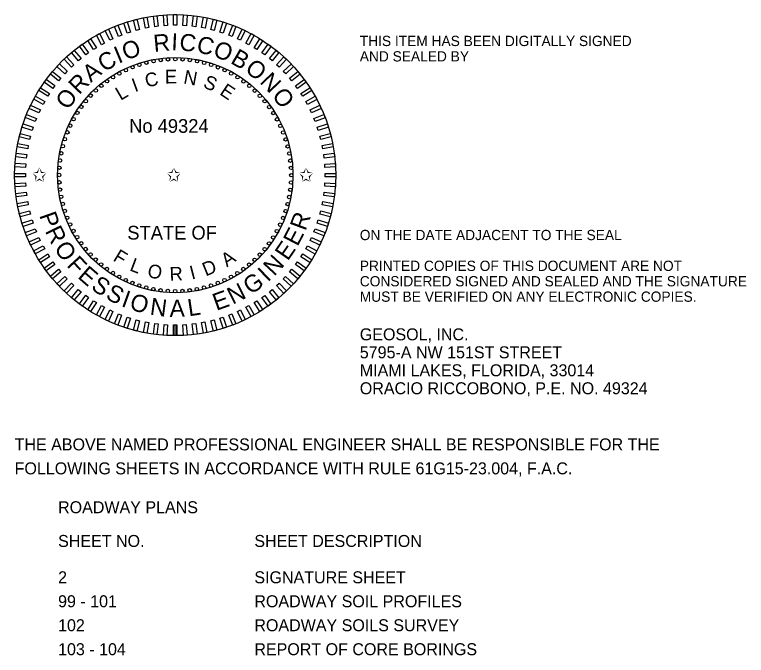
# Model space of a CAD drawing. Extents: x -811 to -790, y -2284 to -2178.
# Drawn here: x -794.327 to -790.055, y -2192.952 to -2189.209 of the extents above; entities that cross this region are included whole.
import ezdxf

# ---------------------------------------------------------------- set-up
doc = ezdxf.new("R2010")
doc.units = 0
for name, color, linetype in [('PlotBorder_dp', 7, 'Continuous'), ('TextMinor', 7, 'Continuous'), ('TextMisc', 7, 'Continuous'), ('TextShtNo', 7, 'Continuous')]:
    doc.layers.add(name, color=color, linetype=linetype)

msp = doc.modelspace()

# ---------------------------------------------------------------- linework, layer by layer
at = {"layer": 'TextMinor'}
for radius in [0.9375, 0.6875]:
    msp.add_circle((-793.3899, -2190.1468), radius, dxfattribs=at)
at = {"layer": 'TextShtNo'}
for p, q in [((-793.3999, -2191.0843), (-793.4001, -2191.0218)), ((-793.3899, -2191.0843), (-793.3901, -2191.0218)), ((-793.3799, -2191.0843), (-793.3801, -2191.0218))]:
    msp.add_line(p, q, dxfattribs=at)
for points in [[(-793.5976, -2189.2967), (-793.6172, -2189.3018), (-793.6327, -2189.2413), (-793.6132, -2189.2363)], [(-793.5438, -2189.2854), (-793.5637, -2189.2892), (-793.5754, -2189.2278), (-793.5555, -2189.224)], [(-793.4895, -2189.2774), (-793.5095, -2189.2799), (-793.5173, -2189.218), (-793.4973, -2189.2155)], [(-793.4347, -2189.2729), (-793.4548, -2189.2741), (-793.4587, -2189.2118), (-793.4386, -2189.2106)], [(-793.3797, -2189.2718), (-793.3999, -2189.2718), (-793.3999, -2189.2093), (-793.3797, -2189.2093)], [(-793.3248, -2189.2741), (-793.3449, -2189.2729), (-793.341, -2189.2106), (-793.3209, -2189.2118)], [(-793.2701, -2189.28), (-793.2901, -2189.2774), (-793.2823, -2189.2155), (-793.2623, -2189.218)], [(-793.2159, -2189.2892), (-793.2357, -2189.2854), (-793.224, -2189.2241), (-793.2042, -2189.2279)], [(-793.1624, -2189.3018), (-793.182, -2189.2968), (-793.1664, -2189.2363), (-793.1469, -2189.2413)], [(-793.7025, -2189.3295), (-793.7213, -2189.3369), (-793.7443, -2189.2789), (-793.7255, -2189.2714)], [(-793.6506, -2189.3115), (-793.6698, -2189.3177), (-793.6891, -2189.2583), (-793.6699, -2189.2521)], [(-793.1098, -2189.3178), (-793.129, -2189.3115), (-793.1097, -2189.2521), (-793.0905, -2189.2584)], [(-793.0583, -2189.337), (-793.0771, -2189.3295), (-793.0541, -2189.2715), (-793.0353, -2189.2789)], [(-793.8025, -2189.3751), (-793.8202, -2189.3848), (-793.8503, -2189.3301), (-793.8326, -2189.3204)], [(-793.7532, -2189.3507), (-793.7715, -2189.3593), (-793.7981, -2189.3028), (-793.7798, -2189.2942)], [(-793.0081, -2189.3594), (-793.0264, -2189.3508), (-792.9998, -2189.2943), (-792.9815, -2189.3029)], [(-792.9594, -2189.3849), (-792.9771, -2189.3752), (-792.947, -2189.3205), (-792.9293, -2189.3302)], [(-793.8502, -2189.4025), (-793.8672, -2189.4134), (-793.9007, -2189.3606), (-793.8836, -2189.3498)], [(-792.9124, -2189.4135), (-792.9295, -2189.4026), (-792.896, -2189.3499), (-792.879, -2189.3607)], [(-793.896, -2189.4329), (-793.9123, -2189.4448), (-793.949, -2189.3943), (-793.9327, -2189.3824)], [(-792.8673, -2189.4449), (-792.8836, -2189.433), (-792.8469, -2189.3825), (-792.8306, -2189.3944)], [(-793.9815, -2189.502), (-793.9962, -2189.5158), (-794.0389, -2189.4703), (-794.0242, -2189.4565)], [(-793.9398, -2189.4661), (-793.9554, -2189.479), (-793.9952, -2189.4309), (-793.9796, -2189.418)], [(-792.8243, -2189.4791), (-792.8398, -2189.4662), (-792.8, -2189.4181), (-792.7845, -2189.431)], [(-792.7835, -2189.5159), (-792.7982, -2189.5021), (-792.7554, -2189.4566), (-792.7407, -2189.4704)], [(-794.0208, -2189.5404), (-794.0346, -2189.5551), (-794.0801, -2189.5124), (-794.0663, -2189.4976)], [(-792.745, -2189.5552), (-792.7589, -2189.5405), (-792.7133, -2189.4978), (-792.6995, -2189.5125)], [(-794.0576, -2189.5812), (-794.0705, -2189.5968), (-794.1186, -2189.5569), (-794.1057, -2189.5414)], [(-792.7092, -2189.5969), (-792.722, -2189.5813), (-792.6739, -2189.5415), (-792.6611, -2189.5571)], [(-794.0918, -2189.6242), (-794.1037, -2189.6406), (-794.1542, -2189.6039), (-794.1423, -2189.5875)], [(-792.676, -2189.6407), (-792.6878, -2189.6244), (-792.6373, -2189.5877), (-792.6255, -2189.604)], [(-794.1232, -2189.6693), (-794.1341, -2189.6864), (-794.1868, -2189.6529), (-794.176, -2189.6359)], [(-792.6456, -2189.6865), (-792.6564, -2189.6695), (-792.6037, -2189.636), (-792.5929, -2189.6531)], [(-794.1518, -2189.7163), (-794.1615, -2189.734), (-794.2162, -2189.7039), (-794.2065, -2189.6863)], [(-792.6182, -2189.7342), (-792.6279, -2189.7165), (-792.5732, -2189.6864), (-792.5635, -2189.7041)], [(-794.1773, -2189.765), (-794.1859, -2189.7833), (-794.2424, -2189.7567), (-794.2338, -2189.7384)], [(-792.5938, -2189.7835), (-792.6024, -2189.7652), (-792.5459, -2189.7386), (-792.5373, -2189.7569)], [(-794.1997, -2189.8152), (-794.2071, -2189.834), (-794.2652, -2189.811), (-794.2578, -2189.7922)], [(-792.5726, -2189.8342), (-792.58, -2189.8154), (-792.5219, -2189.7924), (-792.5145, -2189.8112)], [(-794.2189, -2189.8667), (-794.2252, -2189.8859), (-794.2846, -2189.8666), (-794.2783, -2189.8474)], [(-792.5545, -2189.8861), (-792.5608, -2189.8669), (-792.5014, -2189.8476), (-792.4952, -2189.8668)], [(-794.2349, -2189.9193), (-794.2399, -2189.9389), (-794.3004, -2189.9234), (-794.2954, -2189.9038)], [(-792.5398, -2189.9391), (-792.5448, -2189.9195), (-792.4844, -2189.904), (-792.4793, -2189.9235)], [(-794.2475, -2189.9728), (-794.2513, -2189.9927), (-794.3126, -2189.981), (-794.3088, -2189.9611)], [(-792.5284, -2189.9929), (-792.5322, -2189.973), (-792.4709, -2189.9613), (-792.4671, -2189.9812)], [(-794.2567, -2190.027), (-794.2593, -2190.0471), (-794.3212, -2190.0392), (-794.3187, -2190.0192)], [(-792.5205, -2190.0472), (-792.523, -2190.0272), (-792.4611, -2190.0194), (-792.4585, -2190.0394)], [(-794.2626, -2190.0817), (-794.2638, -2190.1018), (-794.3261, -2190.0979), (-794.3249, -2190.0778)], [(-792.5159, -2190.102), (-792.5172, -2190.0819), (-792.4549, -2190.078), (-792.4536, -2190.0981)], [(-794.2649, -2190.1366), (-794.2649, -2190.1568), (-794.3274, -2190.1568), (-794.3274, -2190.1366)], [(-792.5149, -2190.157), (-792.5149, -2190.1368), (-792.4524, -2190.1368), (-792.4524, -2190.157)], [(-794.2638, -2190.1916), (-794.2626, -2190.2117), (-794.3249, -2190.2157), (-794.3261, -2190.1955)], [(-792.5172, -2190.2119), (-792.516, -2190.1918), (-792.4536, -2190.1957), (-792.4549, -2190.2158)], [(-794.2593, -2190.2464), (-794.2568, -2190.2664), (-794.3187, -2190.2742), (-794.3212, -2190.2542)], [(-792.523, -2190.2666), (-792.5205, -2190.2466), (-792.4586, -2190.2544), (-792.4611, -2190.2744)], [(-794.2513, -2190.3008), (-794.2475, -2190.3206), (-794.3089, -2190.3323), (-794.3127, -2190.3125)], [(-792.5323, -2190.3208), (-792.5285, -2190.301), (-792.4671, -2190.3127), (-792.4709, -2190.3325)], [(-794.24, -2190.3546), (-794.2349, -2190.3741), (-794.2954, -2190.3896), (-794.3004, -2190.3701)], [(-792.5449, -2190.3743), (-792.5399, -2190.3547), (-792.4794, -2190.3703), (-792.4844, -2190.3898)], [(-794.2252, -2190.4075), (-794.219, -2190.4267), (-794.2784, -2190.446), (-794.2846, -2190.4268)], [(-792.5608, -2190.4269), (-792.5546, -2190.4077), (-792.4952, -2190.427), (-792.5014, -2190.4462)], [(-794.2072, -2190.4595), (-794.1998, -2190.4782), (-794.2578, -2190.5012), (-794.2653, -2190.4824)], [(-792.5801, -2190.4784), (-792.5726, -2190.4596), (-792.5146, -2190.4826), (-792.522, -2190.5014)], [(-794.186, -2190.5102), (-794.1774, -2190.5284), (-794.2339, -2190.555), (-794.2425, -2190.5367)], [(-792.6025, -2190.5286), (-792.5939, -2190.5103), (-792.5374, -2190.5369), (-792.546, -2190.5552)], [(-794.1616, -2190.5594), (-794.1519, -2190.5771), (-794.2066, -2190.6072), (-794.2163, -2190.5895)], [(-792.628, -2190.5773), (-792.6183, -2190.5596), (-792.5636, -2190.5897), (-792.5733, -2190.6074)], [(-794.1342, -2190.6071), (-794.1233, -2190.6241), (-794.1761, -2190.6576), (-794.1869, -2190.6405)], [(-792.6565, -2190.6243), (-792.6457, -2190.6072), (-792.593, -2190.6407), (-792.6038, -2190.6577)], [(-794.1038, -2190.6529), (-794.0919, -2190.6692), (-794.1424, -2190.7059), (-794.1543, -2190.6896)], [(-792.688, -2190.6694), (-792.6761, -2190.653), (-792.6256, -2190.6898), (-792.6374, -2190.7061)], [(-794.0706, -2190.6967), (-794.0577, -2190.7123), (-794.1058, -2190.7521), (-794.1187, -2190.7365)], [(-794.0347, -2190.7384), (-794.0209, -2190.7531), (-794.0664, -2190.7958), (-794.0802, -2190.7811)], [(-792.759, -2190.7532), (-792.7452, -2190.7385), (-792.6997, -2190.7813), (-792.7135, -2190.796)], [(-792.7222, -2190.7124), (-792.7093, -2190.6969), (-792.6612, -2190.7367), (-792.674, -2190.7522)], [(-793.9963, -2190.7777), (-793.9816, -2190.7915), (-794.0243, -2190.837), (-794.0391, -2190.8232)], [(-792.7983, -2190.7917), (-792.7836, -2190.7778), (-792.7409, -2190.8234), (-792.7556, -2190.8372)], [(-793.9555, -2190.8145), (-793.9399, -2190.8274), (-793.9797, -2190.8755), (-793.9953, -2190.8627)], [(-792.84, -2190.8275), (-792.8244, -2190.8147), (-792.7846, -2190.8628), (-792.8002, -2190.8756)], [(-793.9125, -2190.8487), (-793.8961, -2190.8606), (-793.9328, -2190.9111), (-793.9492, -2190.8993)], [(-792.8838, -2190.8607), (-792.8675, -2190.8488), (-792.8308, -2190.8994), (-792.8471, -2190.9112)], [(-793.8674, -2190.8802), (-793.8503, -2190.891), (-793.8838, -2190.9437), (-793.9008, -2190.9329)], [(-793.8204, -2190.9087), (-793.8027, -2190.9184), (-793.8328, -2190.9731), (-793.8504, -2190.9634)], [(-792.9773, -2190.9185), (-792.9596, -2190.9088), (-792.9295, -2190.9635), (-792.9472, -2190.9732)], [(-792.9296, -2190.8911), (-792.9126, -2190.8803), (-792.8791, -2190.933), (-792.8962, -2190.9438)], [(-793.7717, -2190.9342), (-793.7534, -2190.9428), (-793.78, -2190.9993), (-793.7983, -2190.9907)], [(-793.0265, -2190.9429), (-793.0083, -2190.9343), (-792.9817, -2190.9908), (-792.9999, -2190.9994)], [(-793.7215, -2190.9566), (-793.7027, -2190.9641), (-793.7257, -2191.0221), (-793.7445, -2191.0147)], [(-793.67, -2190.9759), (-793.6508, -2190.9821), (-793.6701, -2191.0415), (-793.6893, -2191.0352)], [(-793.6174, -2190.9918), (-793.5978, -2190.9968), (-793.6133, -2191.0573), (-793.6329, -2191.0523)], [(-793.1821, -2190.9969), (-793.1626, -2190.9919), (-793.1471, -2191.0523), (-793.1666, -2191.0574)], [(-793.1292, -2190.9822), (-793.11, -2190.9759), (-793.0907, -2191.0353), (-793.1099, -2191.0415)], [(-793.0772, -2190.9641), (-793.0585, -2190.9567), (-793.0355, -2191.0148), (-793.0543, -2191.0222)], [(-793.5639, -2191.0044), (-793.544, -2191.0082), (-793.5557, -2191.0695), (-793.5756, -2191.0658)], [(-793.5097, -2191.0137), (-793.4896, -2191.0162), (-793.4975, -2191.0781), (-793.5175, -2191.0756)], [(-793.455, -2191.0195), (-793.4348, -2191.0207), (-793.4388, -2191.0831), (-793.4589, -2191.0818)], [(-793.4001, -2191.0218), (-793.3799, -2191.0218), (-793.3799, -2191.0843), (-793.4001, -2191.0843)], [(-793.3451, -2191.0208), (-793.325, -2191.0195), (-793.321, -2191.0818), (-793.3412, -2191.0831)], [(-793.2903, -2191.0162), (-793.2703, -2191.0137), (-793.2625, -2191.0756), (-793.2825, -2191.0782)], [(-793.2359, -2191.0082), (-793.2161, -2191.0045), (-793.2044, -2191.0658), (-793.2242, -2191.0696)]]:
    msp.add_lwpolyline(points, close=True, dxfattribs=at)
for centre in [(-793.5987, -2189.5023), (-793.5578, -2189.4905), (-793.5163, -2189.4812), (-793.4742, -2189.4746), (-793.4319, -2189.4706), (-793.3893, -2189.4693), (-793.3468, -2189.4707), (-793.3044, -2189.4748), (-793.2624, -2189.4814), (-793.2209, -2189.4908), (-793.18, -2189.5027), (-793.7158, -2189.5529), (-793.6778, -2189.5336), (-793.6388, -2189.5167), (-793.14, -2189.5171), (-793.1009, -2189.5341), (-793.7524, -2189.5745), (-793.063, -2189.5534), (-793.0264, -2189.5751), (-793.8213, -2189.6245), (-793.7876, -2189.5984), (-792.9912, -2189.5991), (-792.9576, -2189.6252), (-793.8532, -2189.6526), (-792.9257, -2189.6533), (-793.9115, -2189.7145), (-793.8834, -2189.6826), (-792.8956, -2189.6835), (-792.8675, -2189.7154), (-793.9376, -2189.7481), (-792.8415, -2189.7491), (-793.9616, -2189.7833), (-792.8176, -2189.7843), (-793.9833, -2189.8199), (-792.7959, -2189.8209), (-794.0026, -2189.8578), (-792.7767, -2189.8589), (-794.034, -2189.9369), (-794.0196, -2189.8969), (-792.7598, -2189.8979), (-794.0459, -2189.9778), (-792.7454, -2189.938), (-792.7336, -2189.9789), (-794.0552, -2190.0193), (-792.7243, -2190.0204), (-794.0619, -2190.0613), (-792.7177, -2190.0625), (-794.066, -2190.1037), (-792.7137, -2190.1048), (-794.0674, -2190.1462), (-792.7124, -2190.1474), (-794.0661, -2190.1888), (-792.7138, -2190.1899), (-794.0621, -2190.2312), (-792.7178, -2190.2323), (-794.0555, -2190.2732), (-792.7245, -2190.2743), (-794.0462, -2190.3147), (-792.7338, -2190.3158), (-794.0344, -2190.3556), (-792.7457, -2190.3567), (-794.02, -2190.3957), (-792.7602, -2190.3967), (-794.0031, -2190.4348), (-792.7771, -2190.4358), (-793.9838, -2190.4727), (-792.7965, -2190.4737), (-793.9622, -2190.5093), (-792.8182, -2190.5103), (-793.9383, -2190.5446), (-793.9122, -2190.5782), (-792.8421, -2190.5455), (-793.8841, -2190.6102), (-792.8964, -2190.611), (-792.8682, -2190.5791), (-793.8541, -2190.6403), (-792.9265, -2190.641), (-793.8222, -2190.6684), (-793.7885, -2190.6946), (-792.9921, -2190.6952), (-792.9585, -2190.6692), (-793.7534, -2190.7185), (-793.7168, -2190.7402), (-793.064, -2190.7408), (-793.0274, -2190.7191), (-793.6788, -2190.7596), (-793.6398, -2190.7765), (-793.5998, -2190.7909), (-793.1811, -2190.7913), (-793.141, -2190.7769), (-793.1019, -2190.76), (-793.5589, -2190.8029), (-793.5174, -2190.8122), (-793.4754, -2190.8189), (-793.433, -2190.8229), (-793.3899, -2190.8243), (-793.3479, -2190.823), (-793.3055, -2190.819), (-793.2635, -2190.8124), (-793.222, -2190.8031)]:
    msp.add_circle(centre, 0.01, dxfattribs=at)

# ---------------------------------------------------------------- texts
at = {"layer": 'PlotBorder_dp'}
for s, height, p in [('THIS ITEM HAS BEEN DIGITALLY SIGNED ', 0.06, (-792.3122, -2189.393)), ('AND SEALED BY', 0.06, (-792.3122, -2189.483)), ('ON THE DATE ADJACENT TO THE SEAL', 0.06, (-792.3122, -2190.5264)), ('PRINTED COPIES OF THIS DOCUMENT ARE NOT ', 0.06, (-792.3122, -2190.7064)), ('CONSIDERED SIGNED AND SEALED AND THE SIGNATURE ', 0.06, (-792.3122, -2190.7964)), ('MUST BE VERIFIED ON ANY ELECTRONIC COPIES.', 0.06, (-792.3122, -2190.8864)), ('GEOSOL, INC.', 0.07, (-792.3122, -2191.1116)), ('5795-A NW 151ST STREET', 0.07, (-792.3122, -2191.2166)), ('MIAMI LAKES, FLORIDA, 33014', 0.07, (-792.3122, -2191.3216)), ('ORACIO RICCOBONO, P.E. NO. 49324', 0.07, (-792.3122, -2191.4266)), ('THE ABOVE NAMED PROFESSIONAL ENGINEER SHALL BE RESPONSIBLE FOR THE ', 0.07, (-794.3274, -2191.7544)), ('FOLLOWING SHEETS IN ACCORDANCE WITH RULE 61G15-23.004, F.A.C.', 0.07, (-794.3274, -2191.8944)), ('ROADWAY PLANS', 0.07, (-794.0737, -2192.1214))]:
    msp.add_text(s, height=height, dxfattribs=at).set_placement(p)
at = {"layer": 'TextMisc'}
for s, p in [('SHEET NO.', (-794.0737, -2192.3184)), ('SHEET DESCRIPTION', (-792.9278, -2192.3184)), ('2', (-794.0737, -2192.5306)), ('SIGNATURE SHEET', (-792.9278, -2192.5306)), ('99 - 101', (-794.0737, -2192.6706)), ('ROADWAY SOIL PROFILES', (-792.9278, -2192.6706)), ('102', (-794.0737, -2192.8106)), ('ROADWAY SOILS SURVEY', (-792.9278, -2192.8106)), ('103 - 104', (-794.0737, -2192.9506)), ('REPORT OF CORE BORINGS', (-792.9278, -2192.9506))]:
    msp.add_text(s, height=0.07, dxfattribs=at).set_placement(p)
at = {"layer": 'TextShtNo'}
for s, height, rotation, p in [('R', 0.1, 5.3723, (-793.5127, -2189.4277)), ('I', 0.1, 357.5509, (-793.4137, -2189.4176)), ('C', 0.1, 354.0177, (-793.3688, -2189.4175)), ('O', 0.1, 19.1125, (-793.68, -2189.4774)), ('C', 0.1, 346.2809, (-793.2708, -2189.427)), ('O', 0.1, 338.5441, (-793.175, -2189.4496)), ('I', 0.1, 22.6457, (-793.7207, -2189.4966)), ('B', 0.1, 329.8833, (-793.0724, -2189.4899)), ('C', 0.1, 30.3825, (-793.8053, -2189.547)), ('A', 0.1, 38.1495, (-793.8825, -2189.6087)), ('O', 0.1, 322.2793, (-792.9883, -2189.5377)), ('E', 0.08, 0.4186, (-793.4496, -2189.6117)), ('N', 0.08, 349.2914, (-793.3452, -2189.6103)), ('R', 0.1, 45.9708, (-793.9512, -2189.6807)), ('I', 0.08, 20.0117, (-793.6256, -2189.6627)), ('C', 0.08, 12.2025, (-793.5576, -2189.6352)), ('S', 0.08, 337.0221, (-793.2322, -2189.632)), ('N', 0.1, 313.6185, (-792.9011, -2189.6051)), ('E', 0.08, 325.8663, (-793.1356, -2189.6722)), ('O', 0.1, 54.6317, (-794.015, -2189.7705)), ('L', 0.08, 30.4021, (-793.709, -2189.7132)), ('O', 0.1, 305.3683, (-792.8285, -2189.6809)), ('P', 0.1, 289.4055, (-794.1846, -2190.3814)), ('R', 0.1, 69.5134, (-792.6297, -2190.4765)), ('R', 0.1, 296.1458, (-794.1516, -2190.473)), ('E', 0.1, 62.4712, (-792.6759, -2190.5672)), ('O', 0.1, 303.9671, (-794.1001, -2190.5737)), ('E', 0.1, 55.4289, (-792.7328, -2190.6516)), ('F', 0.08, 328.7241, (-793.7579, -2190.6434)), ('A', 0.08, 34.4992, (-793.088, -2190.6862)), ('N', 0.1, 47.1788, (-792.812, -2190.7407)), ('F', 0.1, 312.628, (-794.0277, -2190.6757)), ('L', 0.08, 339.2916, (-793.6606, -2190.7025)), ('D', 0.08, 22.0128, (-793.2118, -2190.7387)), ('E', 0.1, 319.0783, (-793.9643, -2190.744)), ('O', 0.08, 349.6821, (-793.556, -2190.7422)), ('R', 0.08, 2.3398, (-793.4215, -2190.7641)), ('I', 0.08, 14.2037, (-793.2939, -2190.7574)), ('I', 0.1, 43.6456, (-792.8497, -2190.7751)), ('G', 0.1, 35.1115, (-792.9489, -2190.8483)), ('S', 0.1, 326.1206, (-793.8867, -2190.81)), ('N', 0.1, 26.8614, (-793.0542, -2190.9044)), ('S', 0.1, 333.193, (-793.8013, -2190.8661)), ('I', 0.1, 340.2654, (-793.7096, -2190.9113)), ('E', 0.1, 19.8191, (-793.1496, -2190.9398)), ('O', 0.1, 343.7986, (-793.6619, -2190.9295)), ('N', 0.1, 352.4595, (-793.5409, -2190.9615)), ('A', 0.1, 0.7097, (-793.4224, -2190.9748)), ('L', 0.1, 8.4767, (-793.3102, -2190.9716))]:
    msp.add_text(s, height=height, rotation=rotation, dxfattribs=at).set_placement(p)
for s, p in [('No 49324', (-793.6588, -2189.8996)), ('✩', (-794.2249, -2190.1848)), ('✩', (-793.4401, -2190.1848)), ('✩', (-792.6683, -2190.1848)), ('STATE OF', (-793.6696, -2190.523))]:
    msp.add_text(s, height=0.08, dxfattribs=at).set_placement(p)

doc.saveas('drawing.dxf')
